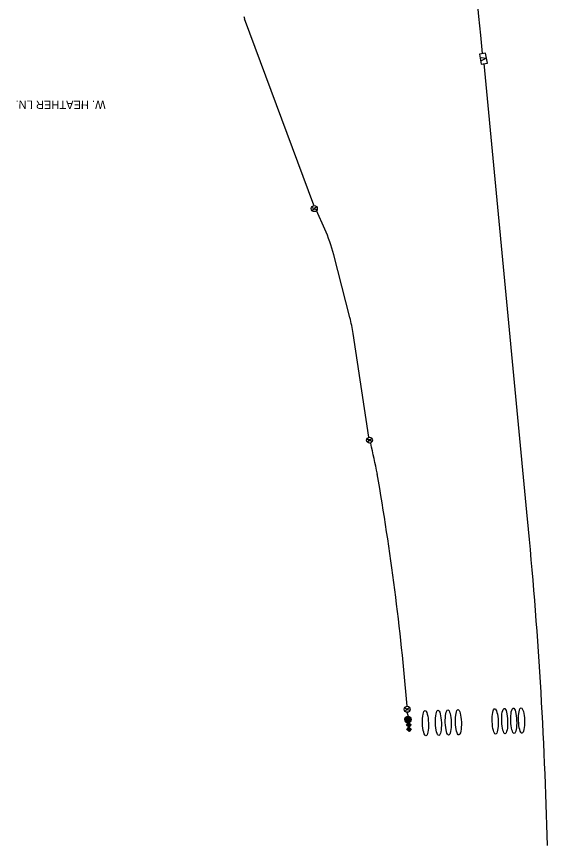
# Model space of a CAD drawing. Extents: x 601562 to 605316, y 332050 to 402250.
# Drawn here: x 603761 to 604432, y 347935 to 348982 of the extents above; entities that cross this region are included whole.
import ezdxf

# ---------------------------------------------------------------- set-up
doc = ezdxf.new("R2010")
doc.units = 0
doc.layers.add('P_FTMS', color=7, linetype='Continuous')
doc.layers.add('P_FTMSConduit', color=7, linetype='Continuous')

# ---------------------------------------------------------------- blocks, each defined once
blk = doc.blocks.new('_U230')
at = {"layer": 'P_FTMS'}
for p, q in [((12.1, 1.6), (-12.2, -0.1)), ((11.8, 3), (-12.1, 1.4)), ((11.9, 2.3), (-12.1, 0.6)), ((12.1, 0.8), (-12.1, -0.8)), ((12.1, 0.1), (-12.1, -1.6)), ((11.6, 3.7), (-12, 2.1)), ((-11.9, 2.5), (-11.4, -4.2)), ((11.3, 4.4), (-11.8, 2.9)), ((11, 5.2), (-11.6, 3.6)), ((10.6, 5.9), (-11.4, 4.4)), ((-11.3, 4.5), (-10.6, -6)), ((10.2, 6.6), (-11, 5.1)), ((9.8, 7.3), (-10.7, 5.9)), ((-10.7, 5.9), (-9.8, -7.2)), ((9.2, 8), (-10.2, 6.6)), ((-10, 6.9), (-9, -8.2)), ((8.6, 8.6), (-9.7, 7.4)), ((-9.3, 7.8), (-8.2, -9)), ((7.8, 9.3), (-9, 8.2)), ((-8.6, 8.5), (-7.4, -9.6)), ((6.9, 10), (-8.2, 9)), ((-8, 9.2), (-6.6, -10.2)), ((-7.3, 9.7), (-5.9, -10.6)), ((5.8, 10.7), (-7.2, 9.8)), ((-6.6, 10.3), (-5.1, -11)), ((4.5, 11.3), (-6, 10.6)), ((-5.9, 10.7), (-4.4, -11.4)), ((-5.1, 11), (-3.6, -11.6)), ((-4.4, 11.3), (-2.9, -11.8)), ((2.5, 11.9), (-4.1, 11.5)), ((-3.7, 11.6), (-2.1, -12)), ((-3, 11.8), (-1.4, -12.1)), ((-2.3, 12), (-0.6, -12.2)), ((-1.6, 12.1), (0.1, -12.2)), ((-0.8, 12.1), (0.8, -12.1)), ((-0.1, 12.2), (1.6, -12.1)), ((0.6, 12.1), (2.3, -11.9)), ((1.4, 12.1), (3, -11.8)), ((2.1, 12), (3.7, -11.6)), ((2.9, 11.8), (4.4, -11.3)), ((3.6, 11.6), (5.1, -11)), ((4.4, 11.3), (5.9, -10.7)), ((5.1, 11), (6.6, -10.2)), ((5.9, 10.6), (7.3, -9.8)), ((6.6, 10.2), (8, -9.2)), ((7.4, 9.7), (8.6, -8.6)), ((8.2, 9), (9.3, -7.8)), ((9, 8.2), (10, -6.9)), ((9.8, 7.2), (10.7, -5.8)), ((10.6, 5.9), (11.3, -4.5)), ((11.5, 4), (11.9, -2.5)), ((12.1, -0.6), (-12, -2.3)), ((12.1, -1.4), (-11.8, -3)), ((12, -2.1), (-11.6, -3.7)), ((11.8, -2.9), (-11.3, -4.4)), ((11.6, -3.6), (-11, -5.1)), ((11.3, -4.4), (-10.7, -5.9)), ((11.1, -5.1), (-10.2, -6.6)), ((10.6, -5.9), (-9.8, -7.3)), ((10.2, -6.6), (-9.2, -8)), ((9.6, -7.4), (-8.5, -8.6)), ((9, -8.2), (-7.8, -9.3)), ((8.2, -9), (-6.9, -10)), ((7.3, -9.8), (-5.8, -10.7)), ((6, -10.6), (-4.5, -11.3)), ((4.1, -11.5), (-2.6, -11.9))]:
    blk.add_line(p, q, dxfattribs=at)
blk.add_circle((0, 0), 12.2, dxfattribs=at)
blk = doc.blocks.new('FMD')
at = {"layer": 'P_FTMS'}
for p, q in [((16.9, 17.6), (-16.9, 17.6)), ((-16.1, 16.1), (-16.1, 18.4)), ((16.1, 16.1), (-16.1, 16.1)), ((15.5, 19), (-15.5, 19)), ((-14.6, 14.6), (-14.6, 19.9)), ((14.6, 14.6), (-14.6, 14.6)), ((14, 20.5), (-14, 20.5)), ((-13.2, 13.2), (-13.2, 21.3)), ((13.2, 13.2), (-13.2, 13.2)), ((12.5, 21.9), (-12.5, 21.9)), ((-11.7, 11.7), (-11.7, 22.8)), ((11.7, 11.7), (-11.7, 11.7)), ((11.1, 23.4), (-11.1, 23.4)), ((-10.2, 10.2), (-10.2, 24.2)), ((10.2, 10.2), (-10.2, 10.2)), ((9.6, 24.9), (-9.6, 24.9)), ((-8.8, 8.8), (-8.8, 25.7)), ((8.8, 8.8), (-8.8, 8.8)), ((8.2, 26.3), (-8.2, 26.3)), ((-7.3, 7.3), (-7.3, 27.2)), ((7.3, 7.3), (-7.3, 7.3)), ((6.7, 27.8), (-6.7, 27.8)), ((-5.9, 5.9), (-5.9, 28.6)), ((5.9, 5.9), (-5.9, 5.9)), ((5.2, 29.3), (-5.2, 29.3)), ((-4.4, 4.4), (-4.4, 30.1)), ((4.4, 4.4), (-4.4, 4.4)), ((3.8, 30.7), (-3.8, 30.7)), ((-2.9, 2.9), (-2.9, 31.6)), ((2.9, 2.9), (-2.9, 2.9)), ((2.3, 32.2), (-2.3, 32.2)), ((-1.5, 1.5), (-1.5, 33)), ((1.5, 1.5), (-1.5, 1.5)), ((0.8, 33.6), (-0.8, 33.6)), ((0, 0), (0, 34.5)), ((1.5, 1.5), (1.5, 33)), ((2.9, 2.9), (2.9, 31.6)), ((4.4, 4.4), (4.4, 30.1)), ((5.9, 5.9), (5.9, 28.6)), ((7.3, 7.3), (7.3, 27.2)), ((8.8, 8.8), (8.8, 25.7)), ((10.2, 10.2), (10.2, 24.2)), ((11.7, 11.7), (11.7, 22.8)), ((13.2, 13.2), (13.2, 21.3)), ((14.6, 14.6), (14.6, 19.9)), ((16.1, 16.1), (16.1, 18.4))]:
    blk.add_line(p, q, dxfattribs=at)
blk.add_lwpolyline([(-17.2, 17.2), (0, 34.5), (17.2, 17.2), (0, 0)], close=True, dxfattribs=at)
blk = doc.blocks.new('FTMS_FCV')
at = {"layer": 'P_FTMS'}
blk.add_line((12.7, 16.3), (0.6, -21.9), dxfattribs=at)
blk.add_lwpolyline([(39.1, 24.4), (-39.1, 24.4), (-39.1, -24.4), (39.1, -24.4)], close=True, dxfattribs=at)
blk.add_lwpolyline([(-12.1, 16.2), (0.6, -21.9)], dxfattribs=at)

msp = doc.modelspace()

# ---------------------------------------------------------------- linework, layer by layer
at = {"layer": 'P_FTMS'}
for centre in [(604137.5, 348739.5), (604207.4, 348446.9), (604255, 348106.9)]:
    msp.add_circle(centre, 3.75, dxfattribs=at)
for centre, start, end in [((604137.1, 348743.9), 222.4831, 328.7387), ((604138, 348735), 42.4831, 148.7387), ((604206.9, 348451.4), 222.4831, 328.7387), ((604207.8, 348442.4), 42.4831, 148.7387), ((604254.6, 348111.3), 222.4831, 328.7387), ((604255.5, 348102.4), 42.4831, 148.7387)]:
    msp.add_arc(centre, 3.75, start, end, dxfattribs=at)
for centre in [(604366.2, 348091.6), (604378.2, 348092), (604389.6, 348092.4), (604399.5, 348092.6), (604278.1, 348089.3), (604294.4, 348089.7), (604306.9, 348090.1), (604319.7, 348090.5)]:
    msp.add_ellipse(centre, major_axis=(-0.5, 16), ratio=0.23471, dxfattribs=at)
at = {"layer": 'P_FTMSConduit'}
for p, q in [((604137.1, 348743.9), (604049.3, 348979.4)), ((604407.2, 348347.3), (604352.4, 348922.7)), ((604256.7, 348097.8), (604255.1, 348102.8))]:
    msp.add_line(p, q, dxfattribs=at)
for points in [[(604150.8, 348713.7), (604140.4, 348737)], [(604182.6, 348601.8), (604162.2, 348681.3)], [(604206.3, 348450.7), (604186.6, 348581.8)]]:
    msp.add_lwpolyline(points, dxfattribs=at)
for centre, radius, start, end in [((586818.9, 347308.2), 17606.6, 5.30276, 7.75042), ((604063.3, 348984.7), 15, 189.5498, 200.4471), ((603968.4, 348631.6), 200, 14.3748, 24.2367), ((603988.8, 348552.1), 200, 8.5267, 14.3748), ((600923.7, 347718.7), 3364.1, 11.7565, 12.4342), ((600891.6, 347826.7), 3375.3, 4.8268, 9.8531), ((598624.1, 347788.6), 5810, 1.4429, 5.51866)]:
    msp.add_arc(centre, radius, start, end, dxfattribs=at)

# ---------------------------------------------------------------- block references
at = {"layer": 'P_FTMS'}
for name, p, xscale, yscale, rotation in [('FTMS_FCV', (604351.3, 348929), 0.1640416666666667, 0.16404166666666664, 100.15149376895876), ('_U230', (604255.9, 348093.9), 0.32808333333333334, 0.3280833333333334, -172.77099164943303), ('FMD', (604259.7, 348087.3), 0.1640416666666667, 0.1640416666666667, 93.12187258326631), ('FMD', (604260, 348081.6), 0.1640416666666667, 0.1640416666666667, 93.12187258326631)]:
    msp.add_blockref(name, p, dxfattribs=dict(at, xscale=xscale, yscale=yscale, rotation=rotation))

# ---------------------------------------------------------------- texts
at = {"layer": 'P_FTMSConduit'}
msp.add_text('W. HEATHER LN.', height=10.5, rotation=179.8354, dxfattribs=at).set_placement((603873.7, 348875.8))

doc.saveas('drawing.dxf')
